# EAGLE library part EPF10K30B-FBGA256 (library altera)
EPF10K30B FLEX 10K family
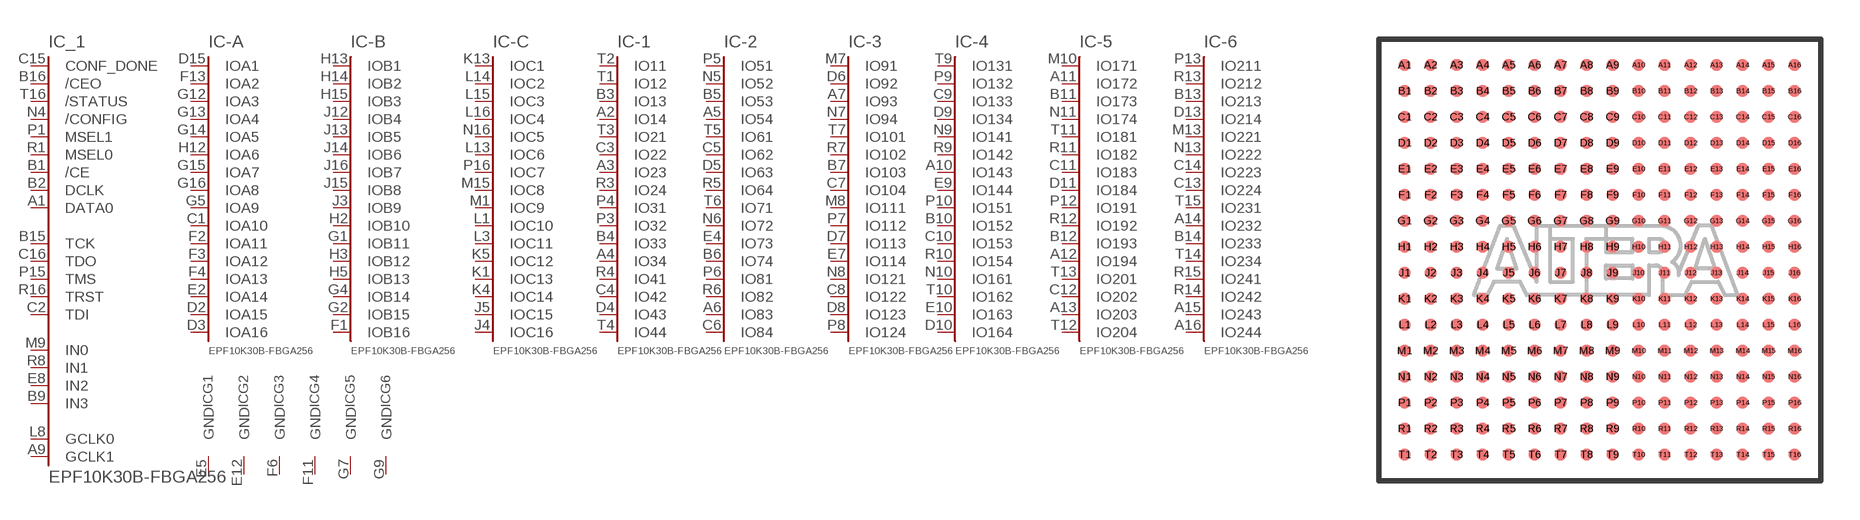
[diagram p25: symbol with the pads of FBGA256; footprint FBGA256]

Designator prefix IC; gates _1=K10-CTRL -A=A16 -B=B16 -C=C16 -1=IO-44 -2=IO-84 -3=IO-124 -4=IO-164 -5=IO-204 -6=IO-244 G1=GND G2=GND G3=GND G4=GND G5=GND G6=GND G7=GND G8=GND G9=GND G10=GND G11=GND G12=GND G13=GND G14=GND G15=GND G16=GND G17=GND G18=GND NC1=NC NC2=NC NC3=NC NC4=NC NC5=NC NC6=NC NC7=NC NC8=NC NC9=NC NC10=NC NC11=NC NC12=NC NC13=NC NC14=NC NC15=NC NC16=NC NC17=NC NC18=NC NC19=NC NC20=NC NC21=NC NC22=NC NC23=NC NC24=NC NC25=NC NC26=NC NC27=NC NC28=NC NC29=NC NC30=NC NC31=NC NC32=NC NC33=NC NC34=NC NC35=NC NC36=NC NC37=NC NC38=NC NC39=NC NC40=NC NC41=NC V1=VCCINT V2=VCCINT V3=VCCINT V4=VCCINT V5=VCCINT V6=VCCINT V7=VCCINT V8=VCCINT V9=VCCINT V10=VCCINT V11=VCCINT V12=VCCINT V13=VCCINT V14=VCCINT V15=VCCINT V16=VCCINT V17=VCCINT V18=VCCINT VO1=VCCIO VO2=VCCIO VO3=VCCIO VO4=VCCIO VO5=VCCIO VO6=VCCIO VO7=VCCIO VO8=VCCIO VO9=VCCIO VO10=VCCIO VO11=VCCIO VO12=VCCIO VO13=VCCIO VO14=VCCIO VO15=VCCIO

## EPF10K30B-FBGA256 (OC_FARNELL: unknown; OC_NEWARK: unknown)  [FBGA256]
A1  _1:DATA0  in
A2  -1:IO14
A3  -1:IO23
A4  -1:IO34
A5  -2:IO54
A6  -2:IO83
A7  -3:IO93
A8  NC1:NC  nc
A9  _1:GCLK1  in
A10  -4:IO143
A11  -5:IO172
A12  -5:IO194
A13  -5:IO203
A14  -6:IO232
A15  -6:IO243
A16  -6:IO244
B1  _1:/CE  in
B2  _1:DCLK  in
B3  -1:IO13
B4  -1:IO33
B5  -2:IO53
B6  -2:IO74
B7  -3:IO103
B8  NC2:NC  nc
B9  _1:IN3  in
B10  -4:IO152
B11  -5:IO173
B12  -5:IO193
B13  -6:IO213
B14  -6:IO233
B15  _1:TCK
B16  _1:/CEO  in
C1  -A:IOA10
C2  _1:TDI
C3  -1:IO22
C4  -1:IO42
C5  -2:IO62
C6  -2:IO84
C7  -3:IO104
C8  -3:IO122
C9  -4:IO133
C10  -4:IO153
C11  -5:IO183
C12  -5:IO202
C13  -6:IO224
C14  -6:IO223
C15  _1:CONF_DONE  in
C16  _1:TDO
D1  NC3:NC  nc
D2  -A:IOA15
D3  -A:IOA16
D4  -1:IO43
D5  -2:IO63
D6  -3:IO92
D7  -3:IO113
D8  -3:IO123
D9  -4:IO134
D10  -4:IO164
D11  -5:IO184
D12  VO1:VCCIO  pwr
D13  -6:IO214
D14  NC4:NC  nc
D15  -A:IOA1
D16  NC5:NC  nc
E1  NC6:NC  nc
E2  -A:IOA14
E3  NC7:NC  nc
E4  -2:IO73
E5  G1:GND  pwr
E6  VO2:VCCIO  pwr
E7  -3:IO114
E8  _1:IN2  in
E9  -4:IO144
E10  -4:IO163
E11  V1:VCC  pwr
E12  G2:GND  pwr
E13  NC8:NC  nc
E14  NC9:NC  nc
E15  NC10:NC  nc
E16  NC11:NC  nc
F1  -B:IOB16
F2  -A:IOA11
F3  -A:IOA12
F4  -A:IOA13
F5  V2:VCC  pwr
F6  G3:GND  pwr
F7  V3:VCC  pwr
F8  VO3:VCCIO  pwr
F9  V4:VCC  pwr
F10  VO4:VCCIO  pwr
F11  G4:GND  pwr
F12  V5:VCC  pwr
F13  -A:IOA2
F14  NC12:NC  nc
F15  NC13:NC  nc
F16  NC14:NC  nc
G1  -B:IOB11
G2  -B:IOB15
G3  NC15:NC  nc
G4  -B:IOB14
G5  -A:IOA9
G6  VO5:VCCIO  pwr
G7  G5:GND  pwr
G8  VO6:VCCIO  pwr
G9  G6:GND  pwr
G10  G7:GND  pwr
G11  VO7:VCCIO  pwr
G12  -A:IOA3
G13  -A:IOA4
G14  -A:IOA5
G15  -A:IOA7
G16  -A:IOA8
H1  NC16:NC  nc
H2  -B:IOB10
H3  -B:IOB12
H4  NC17:NC  nc
H5  -B:IOB13
H6  V6:VCC  pwr
H7  V7:VCC  pwr
H8  G8:GND  pwr
H9  G9:GND  pwr
H10  V8:VCC  pwr
H11  VO8:VCCIO  pwr
H12  -A:IOA6
H13  -B:IOB1
H14  -B:IOB2
H15  -B:IOB3
H16  NC18:NC  nc
J1  NC19:NC  nc
J2  NC20:NC  nc
J3  -B:IOB9
J4  -C:IOC16
J5  -C:IOC15
J6  VO9:VCCIO  pwr
J7  V9:VCC  pwr
J8  G10:GND  pwr
J9  G11:GND  pwr
J10  V10:VCC  pwr
J11  V11:VCC  pwr
J12  -B:IOB4
J13  -B:IOB5
J14  -B:IOB6
J15  -B:IOB8
J16  -B:IOB7
K1  -C:IOC13
K2  NC21:NC  nc
K3  NC22:NC  nc
K4  -C:IOC14
K5  -C:IOC12
K6  VO10:VCCIO  pwr
K7  G12:GND  pwr
K8  VO11:VCCIO  pwr
K9  V12:VCC  pwr
K10  G13:GND  pwr
K11  VO12:VCCIO  pwr
K12  NC23:NC  nc
K13  -C:IOC1
K14  NC24:NC  nc
K15  NC25:NC  nc
K16  NC26:NC  nc
L1  -C:IOC10
L2  NC27:NC  nc
L3  -C:IOC11
L4  NC28:NC  nc
L5  V13:VCC  pwr
L6  G14:GND  pwr
L7  V14:VCC  pwr
L8  _1:GCLK0  in
L9  V15:VCC  pwr
L10  VO13:VCCIO  pwr
L11  G15:GND  pwr
L12  V16:VCC  pwr
L13  -C:IOC6
L14  -C:IOC2
L15  -C:IOC3
L16  -C:IOC4
M1  -C:IOC9
M2  NC29:NC  nc
M3  NC30:NC  nc
M4  NC31:NC  nc
M5  G16:GND  pwr
M6  VO14:VCCIO  pwr
M7  -3:IO91
M8  -3:IO111
M9  _1:IN0  in
M10  -5:IO171
M11  V17:VCC  pwr
M12  G17:GND  pwr
M13  -6:IO221
M14  NC32:NC  nc
M15  -C:IOC8
M16  NC33:NC  nc
N1  NC34:NC  nc
N2  NC35:NC  nc
N3  NC36:NC  nc
N4  _1:/CONFIG  in
N5  -2:IO52
N6  -2:IO72
N7  -3:IO94
N8  -3:IO121
N9  -4:IO141
N10  -4:IO161
N11  -5:IO174
N12  VO15:VCCIO  pwr
N13  -6:IO222
N14  NC37:NC  nc
N15  NC38:NC  nc
N16  -C:IOC5
P1  _1:MSEL1  in
P2  NC39:NC  nc
P3  -1:IO32
P4  -1:IO31
P5  -2:IO51
P6  -2:IO81
P7  -3:IO112
P8  -3:IO124
P9  -4:IO132
P10  -4:IO151
P11  NC40:NC  nc
P12  -5:IO191
P13  -6:IO211
P14  NC41:NC  nc
P15  _1:TMS
P16  -C:IOC7
R1  _1:MSEL0  in
R2  V18:VCC  pwr
R3  -1:IO24
R4  -1:IO41
R5  -2:IO64
R6  -2:IO82
R7  -3:IO102
R8  _1:IN1  in
R9  -4:IO142
R10  -4:IO154
R11  -5:IO182
R12  -5:IO192
R13  -6:IO212
R14  -6:IO242
R15  -6:IO241
R16  _1:TRST
T1  -1:IO12
T2  -1:IO11
T3  -1:IO21
T4  -1:IO44
T5  -2:IO61
T6  -2:IO71
T7  -3:IO101
T8  G18:GND  pwr
T9  -4:IO131
T10  -4:IO162
T11  -5:IO181
T12  -5:IO204
T13  -5:IO201
T14  -6:IO234
T15  -6:IO231
T16  _1:/STATUS  in

## Footprint FBGA256 (pad centres in mm)
Fine Ball Grid Array
smd 0.45 x 0.45: A1 -7.5,7.5; A2 -6.5,7.5; A3 -5.5,7.5; A4 -4.5,7.5; A5 -3.5,7.5; A6 -2.5,7.5; A7 -1.5,7.5; A8 -0.5,7.5; A9 0.5,7.5; A10 1.5,7.5; A11 2.5,7.5; A12 3.5,7.5; A13 4.5,7.5; A14 5.5,7.5; A15 6.5,7.5; A16 7.5,7.5; B1 -7.5,6.5; B2 -6.5,6.5; B3 -5.5,6.5; B4 -4.5,6.5; B5 -3.5,6.5; B6 -2.5,6.5; B7 -1.5,6.5; B8 -0.5,6.5; B9 0.5,6.5; B10 1.5,6.5; B11 2.5,6.5; B12 3.5,6.5; B13 4.5,6.5; B14 5.5,6.5; B15 6.5,6.5; B16 7.5,6.5; C1 -7.5,5.5; C2 -6.5,5.5; C3 -5.5,5.5; C4 -4.5,5.5; C5 -3.5,5.5; C6 -2.5,5.5; C7 -1.5,5.5; C8 -0.5,5.5; C9 0.5,5.5; C10 1.5,5.5; C11 2.5,5.5; C12 3.5,5.5; C13 4.5,5.5; C14 5.5,5.5; C15 6.5,5.5; C16 7.5,5.5; D1 -7.5,4.5; D2 -6.5,4.5; D3 -5.5,4.5; D4 -4.5,4.5; D5 -3.5,4.5; D6 -2.5,4.5; D7 -1.5,4.5; D8 -0.5,4.5; D9 0.5,4.5; D10 1.5,4.5; D11 2.5,4.5; D12 3.5,4.5; D13 4.5,4.5; D14 5.5,4.5; D15 6.5,4.5; D16 7.5,4.5; E1 -7.5,3.5; E2 -6.5,3.5; E3 -5.5,3.5; E4 -4.5,3.5; E5 -3.5,3.5; E6 -2.5,3.5; E7 -1.5,3.5; E8 -0.5,3.5; E9 0.5,3.5; E10 1.5,3.5; E11 2.5,3.5; E12 3.5,3.5; E13 4.5,3.5; E14 5.5,3.5; E15 6.5,3.5; E16 7.5,3.5; F1 -7.5,2.5; F2 -6.5,2.5; F3 -5.5,2.5; F4 -4.5,2.5; F5 -3.5,2.5; F6 -2.5,2.5; F7 -1.5,2.5; F8 -0.5,2.5; F9 0.5,2.5; F10 1.5,2.5; F11 2.5,2.5; F12 3.5,2.5; F13 4.5,2.5; F14 5.5,2.5; F15 6.5,2.5; F16 7.5,2.5; G1 -7.5,1.5; G2 -6.5,1.5; G3 -5.5,1.5; G4 -4.5,1.5; G5 -3.5,1.5; G6 -2.5,1.5; G7 -1.5,1.5; G8 -0.5,1.5; G9 0.5,1.5; G10 1.5,1.5; G11 2.5,1.5; G12 3.5,1.5; G13 4.5,1.5; G14 5.5,1.5; G15 6.5,1.5; G16 7.5,1.5; H1 -7.5,0.5; H2 -6.5,0.5; H3 -5.5,0.5; H4 -4.5,0.5; H5 -3.5,0.5; H6 -2.5,0.5; H7 -1.5,0.5; H8 -0.5,0.5; H9 0.5,0.5; H10 1.5,0.5; H11 2.5,0.5; H12 3.5,0.5; H13 4.5,0.5; H14 5.5,0.5; H15 6.5,0.5; H16 7.5,0.5; J1 -7.5,-0.5; J2 -6.5,-0.5; J3 -5.5,-0.5; J4 -4.5,-0.5; J5 -3.5,-0.5; J6 -2.5,-0.5; J7 -1.5,-0.5; J8 -0.5,-0.5; J9 0.5,-0.5; J10 1.5,-0.5; J11 2.5,-0.5; J12 3.5,-0.5; J13 4.5,-0.5; J14 5.5,-0.5; J15 6.5,-0.5; J16 7.5,-0.5; K1 -7.5,-1.5; K2 -6.5,-1.5; K3 -5.5,-1.5; K4 -4.5,-1.5; K5 -3.5,-1.5; K6 -2.5,-1.5; K7 -1.5,-1.5; K8 -0.5,-1.5; K9 0.5,-1.5; K10 1.5,-1.5; K11 2.5,-1.5; K12 3.5,-1.5; K13 4.5,-1.5; K14 5.5,-1.5; K15 6.5,-1.5; K16 7.5,-1.5; L1 -7.5,-2.5; L2 -6.5,-2.5; L3 -5.5,-2.5; L4 -4.5,-2.5; L5 -3.5,-2.5; L6 -2.5,-2.5; L7 -1.5,-2.5; L8 -0.5,-2.5; L9 0.5,-2.5; L10 1.5,-2.5; L11 2.5,-2.5; L12 3.5,-2.5; L13 4.5,-2.5; L14 5.5,-2.5; L15 6.5,-2.5; L16 7.5,-2.5; M1 -7.5,-3.5; M2 -6.5,-3.5; M3 -5.5,-3.5; M4 -4.5,-3.5; M5 -3.5,-3.5; M6 -2.5,-3.5; M7 -1.5,-3.5; M8 -0.5,-3.5; M9 0.5,-3.5; M10 1.5,-3.5; M11 2.5,-3.5; M12 3.5,-3.5; M13 4.5,-3.5; M14 5.5,-3.5; M15 6.5,-3.5; M16 7.5,-3.5; N1 -7.5,-4.5; N2 -6.5,-4.5; N3 -5.5,-4.5; N4 -4.5,-4.5; N5 -3.5,-4.5; N6 -2.5,-4.5; N7 -1.5,-4.5; N8 -0.5,-4.5; N9 0.5,-4.5; N10 1.5,-4.5; N11 2.5,-4.5; N12 3.5,-4.5; N13 4.5,-4.5; N14 5.5,-4.5; N15 6.5,-4.5; N16 7.5,-4.5; P1 -7.5,-5.5; P2 -6.5,-5.5; P3 -5.5,-5.5; P4 -4.5,-5.5; P5 -3.5,-5.5; P6 -2.5,-5.5; P7 -1.5,-5.5; P8 -0.5,-5.5; P9 0.5,-5.5; P10 1.5,-5.5; P11 2.5,-5.5; P12 3.5,-5.5; P13 4.5,-5.5; P14 5.5,-5.5; P15 6.5,-5.5; P16 7.5,-5.5; R1 -7.5,-6.5; R2 -6.5,-6.5; R3 -5.5,-6.5; R4 -4.5,-6.5; R5 -3.5,-6.5; R6 -2.5,-6.5; R7 -1.5,-6.5; R8 -0.5,-6.5; R9 0.5,-6.5; R10 1.5,-6.5; R11 2.5,-6.5; R12 3.5,-6.5; R13 4.5,-6.5; R14 5.5,-6.5; R15 6.5,-6.5; R16 7.5,-6.5; T1 -7.5,-7.5; T2 -6.5,-7.5; T3 -5.5,-7.5; T4 -4.5,-7.5; T5 -3.5,-7.5; T6 -2.5,-7.5; T7 -1.5,-7.5; T8 -0.5,-7.5; T9 0.5,-7.5; T10 1.5,-7.5; T11 2.5,-7.5; T12 3.5,-7.5; T13 4.5,-7.5; T14 5.5,-7.5; T15 6.5,-7.5; T16 7.5,-7.5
